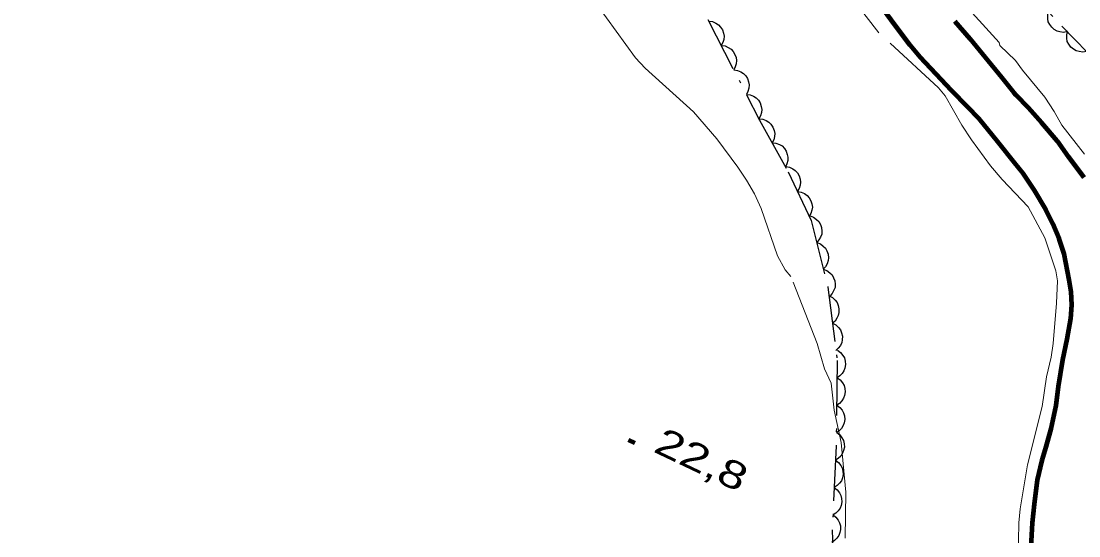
# Model space of a CAD drawing. Extents: x 356765 to 358572, y 5103174 to 5104650.
# Drawn here: x 357194.9 to 357252.7, y 5104231.8 to 5104260 of the extents above; entities that cross this region are included whole.
import ezdxf

# ---------------------------------------------------------------- set-up
doc = ezdxf.new("R2010")
doc.units = 0
doc.header["$LTSCALE"] = 0.6
doc.linetypes.add('DOT_DASHED', pattern=[7.7, 5, -1.2, 0.3, -1.2])
doc.linetypes.add('LONG_DASHED', pattern=[7.5, 6, -1.5])
for name, color, linetype, lineweight in [('2', 7, 'Continuous', 13), ('3', 7, 'Continuous', 140), ('4', 7, 'Continuous', 90), ('44', 7, 'Continuous', 25)]:
    doc.layers.add(name, color=color, linetype=linetype, lineweight=lineweight)

msp = doc.modelspace()

# ---------------------------------------------------------------- linework, layer by layer
at = {"layer": '2', "linetype": 'LONG_DASHED'}
for points in [[(357235.98, 5104274.17), (357236.4, 5104273.63), (357237.85, 5104272.09), (357241.31, 5104267.3), (357242.54, 5104265.84), (357243.08, 5104265.09), (357244.48, 5104263.5), (357245.56, 5104261.91), (357246.05, 5104261.3), (357248.31, 5104258.82), (357248.35, 5104258.66), (357249.2, 5104257.84), (357249.59, 5104257.3), (357250.8, 5104255.83), (357251.32, 5104255.05), (357251.73, 5104254.3), (357252.97, 5104252.71)], [(357246.79, 5104253.5), (357246.27, 5104254.29), (357245.36, 5104255.9), (357244.99, 5104256.34), (357241.74, 5104259.34), (357240.48, 5104260.96), (357238.63, 5104263.53), (357238.11, 5104264.36), (357237.08, 5104265.79), (357236.02, 5104267.65), (357235.52, 5104268.41), (357234.81, 5104269.26), (357234.4, 5104269.63), (357233.21, 5104270.55), (357232.76, 5104271.01), (357232.25, 5104271.69)], [(357239.89, 5104231.72), (357239.93, 5104234.24), (357239.67, 5104236.94), (357239.29, 5104238.72), (357239.12, 5104240.19), (357238.77, 5104240.97), (357238.37, 5104242.37), (357236.93, 5104246.03), (357236.62, 5104246.38), (357236.2, 5104247.16), (357235.31, 5104249.75), (357234.94, 5104250.55), (357234.51, 5104251.3), (357234.03, 5104252.01), (357232.88, 5104253.55), (357231.61, 5104255.03), (357228.96, 5104257.42), (357228.44, 5104257.98), (357225.72, 5104261.72)], [(357249.34, 5104230.58), (357249.39, 5104232.55), (357249.45, 5104233.32), (357249.86, 5104235.73), (357250.65, 5104238.91), (357250.9, 5104240.54), (357251.14, 5104241.61), (357251.25, 5104242.37), (357251.44, 5104244.57), (357251.5, 5104245.79), (357251.4, 5104246.34), (357250.8, 5104248.13), (357249.9, 5104249.83), (357248.47, 5104251.33), (357247.83, 5104252.08), (357246.79, 5104253.5)]]:
    msp.add_lwpolyline(points, dxfattribs=at)
at = {"layer": '3'}
msp.add_line((357228.05, 5104237.1), (357228.41, 5104236.93), dxfattribs=at)
at = {"layer": '4'}
for points in [[(357246.59, 5104255.29), (357245.7, 5104256.19), (357244.86, 5104257.09), (357243.99, 5104258.01), (357243.45, 5104258.68), (357242.6, 5104259.78), (357241.8, 5104260.87), (357240.88, 5104262.11), (357240.18, 5104262.97), (357239.14, 5104264.25), (357238.29, 5104265.38), (357237.44, 5104266.58), (357236.67, 5104267.63), (357235.91, 5104268.59), (357234.92, 5104269.86), (357234.04, 5104270.9), (357233.13, 5104271.96), (357232.97, 5104272.17)], [(357245.88, 5104259.99), (357246.72, 5104259.01), (357247.55, 5104258.01), (357248.46, 5104256.91), (357249.11, 5104256.09), (357249.22, 5104255.96), (357249.89, 5104255.26), (357250.62, 5104254.44), (357251.47, 5104253.44), (357252.07, 5104252.59), (357252.93, 5104251.43)], [(357250.06, 5104231.23), (357250.13, 5104232.55), (357250.24, 5104233.57), (357250.41, 5104234.9), (357250.65, 5104235.99), (357250.88, 5104236.71), (357251.15, 5104237.69), (357251.43, 5104238.98), (357251.55, 5104240.01), (357251.79, 5104241.46), (357252.03, 5104242.59), (357252.22, 5104243.73), (357252.28, 5104244.47), (357252.24, 5104245.18), (357252.14, 5104245.84), (357251.85, 5104247.26), (357251.59, 5104248.09), (357251.24, 5104248.91), (357250.85, 5104249.68), (357250.24, 5104250.72), (357249.61, 5104251.65), (357249.14, 5104252.24), (357248.21, 5104253.4), (357247.19, 5104254.66), (357246.59, 5104255.29)]]:
    msp.add_lwpolyline(points, dxfattribs=at)
at = {"layer": '44', "linetype": 'DOT_DASHED'}
for points in [[(357253.82, 5104257.56), (357250.95, 5104260.53), (357248.13, 5104262.88), (357245.1, 5104265.55), (357239.57, 5104270.78), (357234.96, 5104275.89), (357230.8, 5104280.75), (357227.55, 5104285.5), (357225.3, 5104288.51), (357223.44, 5104291.51), (357222.38, 5104293.47), (357221.31, 5104295.44), (357219.37, 5104298.28), (357217.32, 5104300.6), (357213.49, 5104306.06), (357210.73, 5104309.56), (357208.16, 5104312.36)], [(357191.98, 5104271.17), (357195.46, 5104273.16), (357198.76, 5104274.85), (357201.45, 5104276.49), (357204.76, 5104278.18), (357207.28, 5104279.52), (357209.45, 5104279.88), (357211.29, 5104279.65), (357212.8, 5104279.19), (357215.37, 5104278.16), (357218.67, 5104276.32), (357221.42, 5104274.21), (357224.97, 5104271.06), (357227.28, 5104267.81), (357230.03, 5104263.93), (357232.39, 5104260.07), (357235.22, 5104254.58), (357236.78, 5104251.75), (357238.04, 5104249.08), (357238.95, 5104245.44), (357239.46, 5104241.43), (357239.4, 5104236.76), (357239.19, 5104232.18), (357239.27, 5104228.8)]]:
    msp.add_lwpolyline(points, dxfattribs=at)
at = {"layer": '44'}
for points in [[(357252.04, 5104259.41), (357251.83, 5104259.37), (357251.63, 5104259.4), (357251.47, 5104259.44), (357251.32, 5104259.53), (357251.18, 5104259.65), (357251.07, 5104259.81), (357250.99, 5104259.95), (357250.96, 5104260.12), (357250.96, 5104260.31), (357250.99, 5104260.49)], [(357232.43, 5104259.98), (357232.64, 5104259.96), (357232.83, 5104259.88), (357232.97, 5104259.79), (357233.09, 5104259.66), (357233.19, 5104259.51), (357233.24, 5104259.32), (357233.28, 5104259.16), (357233.26, 5104258.99), (357233.21, 5104258.81), (357233.12, 5104258.65)], [(357253.08, 5104258.33), (357252.87, 5104258.29), (357252.67, 5104258.32), (357252.51, 5104258.36), (357252.36, 5104258.45), (357252.22, 5104258.57), (357252.11, 5104258.73), (357252.03, 5104258.87), (357252, 5104259.05), (357252, 5104259.23), (357252.04, 5104259.41)], [(357233.12, 5104258.65), (357233.33, 5104258.63), (357233.51, 5104258.54), (357233.66, 5104258.46), (357233.77, 5104258.33), (357233.87, 5104258.17), (357233.93, 5104257.99), (357233.96, 5104257.83), (357233.94, 5104257.65), (357233.89, 5104257.48), (357233.81, 5104257.32)], [(357233.81, 5104257.32), (357234.02, 5104257.29), (357234.2, 5104257.21), (357234.34, 5104257.13), (357234.46, 5104257), (357234.56, 5104256.84), (357234.62, 5104256.66), (357234.65, 5104256.5), (357234.63, 5104256.32), (357234.58, 5104256.14), (357234.5, 5104255.98)], [(357234.5, 5104255.98), (357234.7, 5104255.96), (357234.89, 5104255.88), (357235.03, 5104255.79), (357235.15, 5104255.66), (357235.25, 5104255.51), (357235.31, 5104255.32), (357235.34, 5104255.16), (357235.32, 5104254.99), (357235.27, 5104254.81), (357235.18, 5104254.65)], [(357235.18, 5104254.65), (357235.39, 5104254.63), (357235.58, 5104254.55), (357235.72, 5104254.47), (357235.84, 5104254.35), (357235.95, 5104254.19), (357236.01, 5104254.01), (357236.05, 5104253.85), (357236.03, 5104253.68), (357235.99, 5104253.5), (357235.91, 5104253.34)], [(357235.91, 5104253.34), (357236.11, 5104253.32), (357236.3, 5104253.24), (357236.45, 5104253.16), (357236.57, 5104253.03), (357236.67, 5104252.88), (357236.73, 5104252.7), (357236.77, 5104252.54), (357236.76, 5104252.36), (357236.71, 5104252.18), (357236.63, 5104252.02)], [(357236.65, 5104252.03), (357236.85, 5104252), (357237.04, 5104251.91), (357237.17, 5104251.82), (357237.29, 5104251.69), (357237.38, 5104251.53), (357237.43, 5104251.34), (357237.46, 5104251.18), (357237.43, 5104251.01), (357237.38, 5104250.83), (357237.29, 5104250.68)], [(357237.29, 5104250.68), (357237.49, 5104250.64), (357237.68, 5104250.56), (357237.81, 5104250.46), (357237.93, 5104250.33), (357238.02, 5104250.17), (357238.07, 5104249.99), (357238.1, 5104249.82), (357238.07, 5104249.65), (357238.02, 5104249.47), (357237.93, 5104249.32)], [(357237.98, 5104249.34), (357238.17, 5104249.26), (357238.33, 5104249.14), (357238.45, 5104249.03), (357238.54, 5104248.87), (357238.6, 5104248.7), (357238.61, 5104248.51), (357238.61, 5104248.34), (357238.55, 5104248.18), (357238.46, 5104248.02), (357238.34, 5104247.88)], [(357238.34, 5104247.88), (357238.54, 5104247.81), (357238.7, 5104247.69), (357238.82, 5104247.57), (357238.9, 5104247.42), (357238.96, 5104247.24), (357238.98, 5104247.05), (357238.97, 5104246.89), (357238.91, 5104246.72), (357238.82, 5104246.56), (357238.7, 5104246.43)], [(357238.7, 5104246.43), (357238.9, 5104246.35), (357239.06, 5104246.23), (357239.18, 5104246.12), (357239.26, 5104245.96), (357239.32, 5104245.79), (357239.34, 5104245.6), (357239.34, 5104245.43), (357239.28, 5104245.27), (357239.19, 5104245.1), (357239.07, 5104244.97)], [(357239.01, 5104244.96), (357239.2, 5104244.87), (357239.34, 5104244.73), (357239.45, 5104244.6), (357239.51, 5104244.43), (357239.55, 5104244.25), (357239.54, 5104244.06), (357239.52, 5104243.9), (357239.44, 5104243.74), (357239.34, 5104243.59), (357239.2, 5104243.47)], [(357239.2, 5104243.47), (357239.39, 5104243.38), (357239.53, 5104243.24), (357239.64, 5104243.11), (357239.7, 5104242.95), (357239.74, 5104242.76), (357239.73, 5104242.57), (357239.71, 5104242.41), (357239.63, 5104242.25), (357239.52, 5104242.1), (357239.39, 5104241.98)], [(357239.47, 5104241.99), (357239.64, 5104241.87), (357239.76, 5104241.71), (357239.85, 5104241.57), (357239.89, 5104241.4), (357239.91, 5104241.21), (357239.87, 5104241.02), (357239.82, 5104240.87), (357239.73, 5104240.72), (357239.6, 5104240.59), (357239.45, 5104240.49)], [(357239.45, 5104240.49), (357239.62, 5104240.37), (357239.75, 5104240.21), (357239.83, 5104240.07), (357239.87, 5104239.9), (357239.89, 5104239.71), (357239.85, 5104239.52), (357239.81, 5104239.37), (357239.71, 5104239.22), (357239.58, 5104239.09), (357239.43, 5104238.99)], [(357239.43, 5104238.99), (357239.6, 5104238.87), (357239.73, 5104238.71), (357239.81, 5104238.57), (357239.85, 5104238.4), (357239.87, 5104238.21), (357239.83, 5104238.02), (357239.79, 5104237.87), (357239.69, 5104237.72), (357239.56, 5104237.59), (357239.41, 5104237.49)], [(357239.43, 5104237.49), (357239.6, 5104237.36), (357239.72, 5104237.2), (357239.8, 5104237.05), (357239.84, 5104236.88), (357239.85, 5104236.7), (357239.81, 5104236.51), (357239.75, 5104236.36), (357239.65, 5104236.21), (357239.52, 5104236.08), (357239.36, 5104235.99)], [(357239.36, 5104235.99), (357239.53, 5104235.86), (357239.65, 5104235.7), (357239.73, 5104235.56), (357239.77, 5104235.38), (357239.78, 5104235.2), (357239.74, 5104235.01), (357239.69, 5104234.86), (357239.58, 5104234.72), (357239.45, 5104234.59), (357239.3, 5104234.49)], [(357239.3, 5104234.49), (357239.46, 5104234.37), (357239.58, 5104234.2), (357239.66, 5104234.06), (357239.7, 5104233.89), (357239.71, 5104233.7), (357239.67, 5104233.51), (357239.62, 5104233.36), (357239.51, 5104233.22), (357239.38, 5104233.09), (357239.23, 5104232.99)], [(357239.23, 5104232.99), (357239.39, 5104232.87), (357239.52, 5104232.7), (357239.59, 5104232.56), (357239.63, 5104232.39), (357239.64, 5104232.2), (357239.6, 5104232.02), (357239.55, 5104231.86), (357239.44, 5104231.72), (357239.31, 5104231.59), (357239.16, 5104231.49)]]:
    msp.add_lwpolyline(points, dxfattribs=at)

# ---------------------------------------------------------------- texts
at = {"layer": '3', "width": 1.35}
msp.add_text('22,8   ', height=1.5, rotation=334.619, dxfattribs=at).set_placement((357229.35, 5104236.47))

doc.saveas('drawing.dxf')
